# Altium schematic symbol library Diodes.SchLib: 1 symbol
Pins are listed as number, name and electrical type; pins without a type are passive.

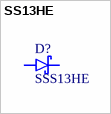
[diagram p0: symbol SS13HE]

## SS13HE
designator D?, comment SSS13HE
Surface Mount Schottky Barrier Rectifier.; Manufacturer: ON Semiconductor; Forward Voltage Max.: 550mV; Forward Current: 1A; Forward Surge Current Max: 25A
footprint SOD-323HE
pins: 1 C, 2 A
